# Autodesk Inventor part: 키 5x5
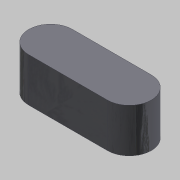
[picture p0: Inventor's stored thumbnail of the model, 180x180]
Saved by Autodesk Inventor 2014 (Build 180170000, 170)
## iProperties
Created: 2016-04
Part Number: 키 5x5
Document SubType Name: Modeling
Designer: mdu
Density: 7.86 g/cm^3
Mass: 2.54015 g
Surface Area: 2.9781 cm^2
Volume: 0.323175 cm^3
Material: 강철, 연강
Appearance: 강철 - 광택
Author: mdu
Revision Number: 1
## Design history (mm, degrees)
sketch "스케치1"
  geometry: L1 (-4.5, -2.5)-(4.5, -2.5); L2 (4.5, 2.5)-(-4.5, 2.5); A1 r 2.5 centre (4.5, 0) between (4.5, -2.5) and (4.5, 2.5); A2 r 2.5 centre (-4.5, 0) between (-4.5, 2.5) and (-4.5, -2.5); 2 further points
  constraints: 4 end point, 4 point on circle, 4 tangent, 2 centre point, 1 horizontal, 1 horizontal alignment, 1 midpoint, 1 parallel, 1 vertical alignment
  dimensions: "d0" = 5 distance between parallel lines of L1 L2; "d1" = 14 dimension on A1 A2
extrude "돌출1" new body sketch "스케치1" stored distance "d2" = 5; taper "d3" = 0 deg
node "솔리드1"
